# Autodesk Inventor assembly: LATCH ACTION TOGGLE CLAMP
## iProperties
Title: LATCH ACTION TOGGLE CLAMP
Author: TOM MORNESS
Keywords: type 351
Comments: Drive Open Angle in part 351_3512
Revision Number: 00
Created: 2002-01
Part Number: 351
Document SubType Name: Assembly
Designer: tomm
Project: 1
Description: DE-STA-CO LATCH ACTION TYPE
Vendor: 351
Category: purchase
Manager: A43
Company: DE-STA-CO
Control State: 0
Master: False
Checked Out: False
Last Check In Date: 2002-01-29
PropertySet Name: Design Tracking Control
Last Check In By: tomm
Shininess: 0.0
PropertySet Name: _Private Model Information
Density: 7.175161085510009
Volume: 35.904638361407855
Area: 293.8019187086728
PropertySet Name: Model Information
